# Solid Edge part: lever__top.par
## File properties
Author: vinurabandara
Template: iso metric part.par
Last saved by: Nimesh.N
Revision: 2
Application: Solid Edge
Username: Nimesh.N
Density: 1024.000 kg/m^3
Accuracy: 0.990
Material: Plastic ABS (extra strong)
Face Style: Red
Fill Style: Normal Grid
Grouping: Non-metals
LibraryName: Materials-GOST
Coef. of Thermal Exp: 9e-05
Thermal Conductivity: 0.2
Specific Heat: 0.0
Modulus of Elasticity: 1378951400.0
Poisson's Ratio: 0.4
Yield Stress: 31026406.5
Ultimate Stress: 0.0
Elongation: 0.0
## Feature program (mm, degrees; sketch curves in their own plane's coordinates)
sketch for "unnamed RevolvedProtrusion 1" plane through (0, 0, 0) normal (0, -1, 0) x-axis (1, 0, 0)
  line (0, 27.5) -> (0, -40)
  line (0, -40) -> (-10, -40)
  line (-27.0588, -1.0086) -> (-10, -40)
  arc centre (-22.478, 0.9955) radius 5 from (-27.4731, 1.2168) to (-27.0588, -1.0086) ccw
revolve "unnamed RevolvedProtrusion 1" add full turn 360 deg about sketch line (0, 32.4432) -> (0, 18.1199)
sketch for "unnamed Cutout 1" plane through (0, 0, -40) normal (0, 0, -1) x-axis (1, 0, 0)
  circle centre (0, 0) radius 6
extrude "unnamed Cutout 1" cut finite 30 along -normal
thread "unnamed Thread 1"
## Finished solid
Body 1: solid body, 6 faces, 5 edges, 0 vertices.
  Faces by surface: plane 2, cone 1, cylinder 1, sphere 1, torus 1
  Edges by curve: circle 5
Bounding box of the edges (mm; curved faces can reach further): 54.946 x 54.946 x 41.217, from (-27.4731, -27.4731, -40) to (27.4731, 27.4731, 1.2168).
Cylindrical faces by radius (mm): R6 x1
Conical faces (half-angle, radius in mm at the cone's reference point): 23.6294 deg R10 x1
Toroidal faces (ring radius, tube radius in mm): R22.478 r5 x1
Spherical faces by radius (mm): R27.5 x1
Planar faces by outward normal: -z 2
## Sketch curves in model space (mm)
line (-37.7423, 0, 0) -> (46.1677, 0, 0)
line (0, 0, 32.4432) -> (0, 0, 18.1199)
line (0, 0, 27.5) -> (0, 0, -40)
line (0, 0, -40) -> (-10, 0, -40)
line (-27.0588, 0, -1.0086) -> (-10, 0, -40)
arc centre (-22.478, 0, 0.9955) radius 5 from (-27.4731, 0, 1.2168) through (-27.3935, 0, 0.0803) to (-27.0588, 0, -1.0086)
arc centre (0, 0, 0) radius 27.5 from (-27.4731, 0, 1.2168) through (-19.0104, 0, 19.871) to (0, 0, 27.5)
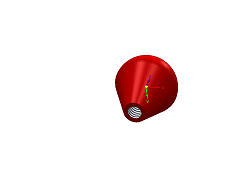
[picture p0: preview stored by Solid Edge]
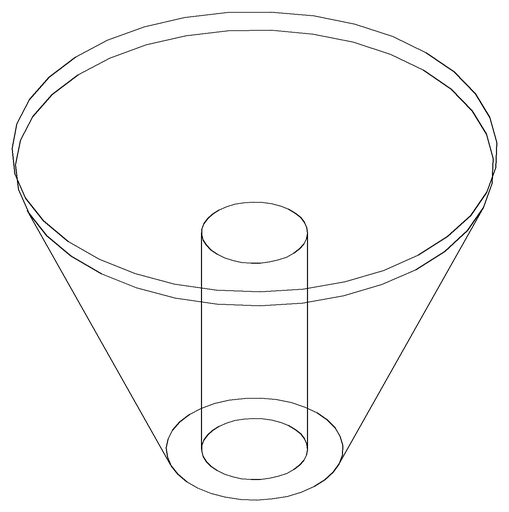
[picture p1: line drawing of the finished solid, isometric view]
